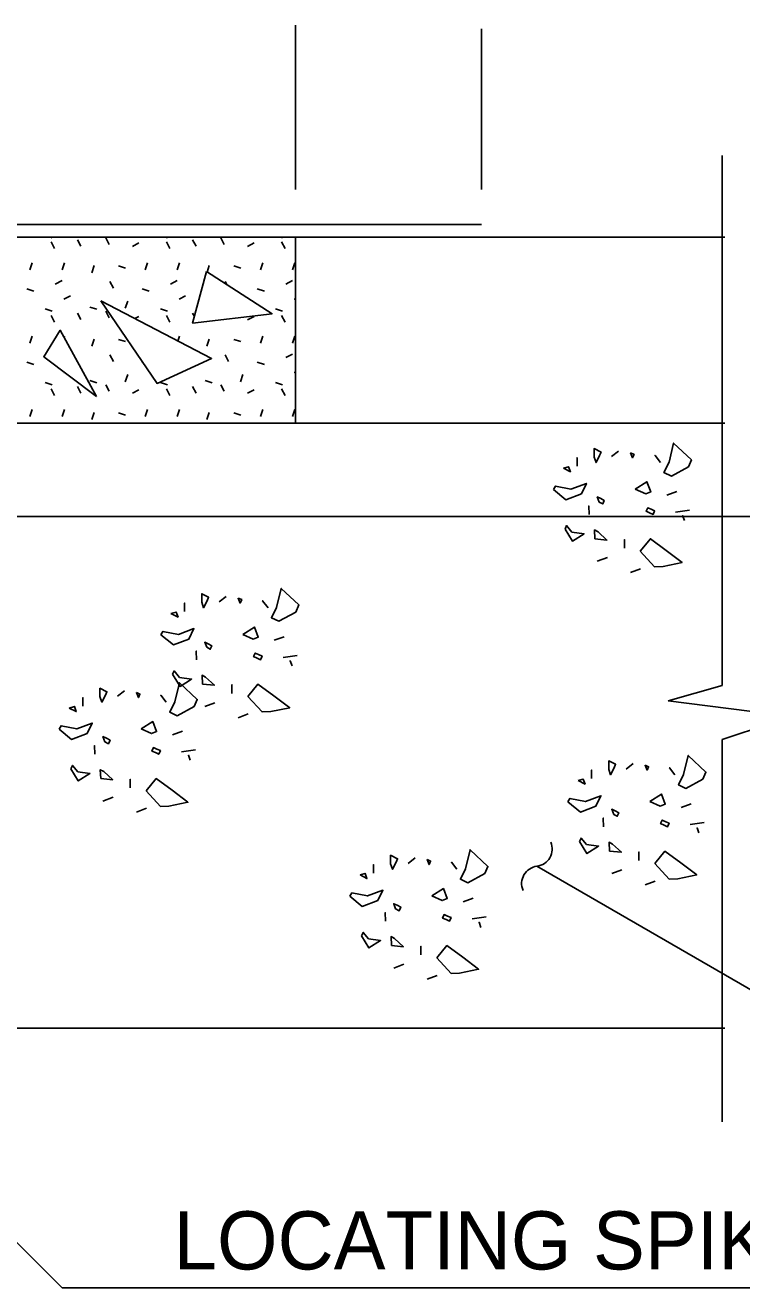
# Model space of a CAD drawing. Extents: x 0 to 11.3, y 0 to 7.8.
# Drawn here: x 3.931 to 4.573, y 1.625 to 2.755 of the extents above; entities that cross this region are included whole.
import ezdxf

# ---------------------------------------------------------------- set-up
doc = ezdxf.new("R2010")
doc.units = 0
for name, color, linetype in [('BRDG_ANNO_General-Notes', 7, 'Continuous'), ('BRDG_BASE_Obj-Line', 7, 'Continuous'), ('BRDG_BASE_Pattern', 7, 'Continuous')]:
    doc.layers.add(name, color=color, linetype=linetype)

msp = doc.modelspace()

# ---------------------------------------------------------------- linework, layer by layer
at = {"layer": 'BRDG_ANNO_General-Notes'}
for p, q in [((4.1734, 2.6081), (4.1734, 2.7552)), ((4.3401, 2.6081), (4.3401, 2.7519)), ((3.4093, 2.3154), (4.8358, 2.3154)), ((3.3467, 2.2423), (3.9645, 1.6245)), ((4.7803, 1.7765), (4.3897, 2.002)), ((4.6945, 1.6245), (3.9645, 1.6245))]:
    msp.add_line(p, q, dxfattribs=at)
for centre, start, end in [((4.3878, 2.0175), 276.8706, 23.1308), ((4.3916, 1.9865), 96.8706, 203.1308)]:
    msp.add_arc(centre, 0.0156, start, end, dxfattribs=at)
at = {"layer": 'BRDG_BASE_Obj-Line'}
for p, q in [((4.5557, 2.6385), (4.5557, 2.164)), ((4.3401, 2.5769), (2.3401, 2.5769)), ((2.5067, 2.5654), (4.1734, 2.5654)), ((3.954, 2.5654), (3.9557, 2.5648)), ((3.9547, 2.5611), (3.9578, 2.5552)), ((3.9782, 2.5631), (3.9812, 2.5573)), ((4.0065, 2.5589), (4.0035, 2.5648)), ((4.0332, 2.5602), (4.0274, 2.5572)), ((4.0571, 2.5654), (4.0589, 2.5648)), ((4.0579, 2.5611), (4.0609, 2.5552)), ((4.0814, 2.5631), (4.0844, 2.5573)), ((4.1097, 2.5589), (4.1067, 2.5648)), ((4.1364, 2.5602), (4.1306, 2.5572)), ((4.1603, 2.5654), (4.162, 2.5648)), ((4.1611, 2.5611), (4.1641, 2.5552)), ((4.5581, 2.5654), (4.1734, 2.5654)), ((4.1734, 2.3987), (4.1734, 2.5654)), ((3.9377, 2.5425), (3.9357, 2.5362)), ((3.9665, 2.5424), (3.9644, 2.5361)), ((3.991, 2.5336), (3.9931, 2.5399)), ((4.0214, 2.5376), (4.0151, 2.5396)), ((4.0409, 2.5425), (4.0389, 2.5362)), ((4.0696, 2.5424), (4.0676, 2.5361)), ((4.0944, 2.5342), (4.0963, 2.5399)), ((4.1245, 2.5376), (4.1183, 2.5396)), ((4.1441, 2.5425), (4.1421, 2.5362)), ((4.1728, 2.5424), (4.1707, 2.5361)), ((3.9644, 2.5265), (3.9584, 2.5234)), ((4.0104, 2.5198), (4.0073, 2.5257)), ((4.0676, 2.5265), (4.0616, 2.5234)), ((4.1119, 2.523), (4.1105, 2.5257)), ((4.1707, 2.5265), (4.1648, 2.5234)), ((3.9329, 2.5191), (3.9392, 2.5171)), ((3.966, 2.5098), (3.9719, 2.5129)), ((4.0361, 2.5191), (4.0424, 2.5171)), ((4.0692, 2.5098), (4.0751, 2.5129)), ((4.1393, 2.5191), (4.1456, 2.5171)), ((4.1724, 2.5098), (4.1734, 2.5103)), ((3.9494, 2.5011), (3.9557, 2.4991)), ((3.9957, 2.5008), (3.9894, 2.5028)), ((4.0065, 2.4931), (4.0035, 2.4991)), ((4.0211, 2.5018), (4.0232, 2.5081)), ((4.0526, 2.5011), (4.0589, 2.4991)), ((4.1557, 2.5011), (4.162, 2.4991)), ((3.9547, 2.4954), (3.9578, 2.4894)), ((3.9782, 2.4974), (3.9812, 2.4916)), ((4.0332, 2.4945), (4.0296, 2.4926)), ((4.0579, 2.4954), (4.0609, 2.4894)), ((4.0814, 2.4974), (4.083, 2.4943)), ((4.1364, 2.4945), (4.1306, 2.4915)), ((4.1611, 2.4954), (4.1641, 2.4894)), ((3.9377, 2.4768), (3.9357, 2.4705)), ((3.9665, 2.4767), (3.9662, 2.4759)), ((4.0696, 2.4767), (4.0682, 2.4724)), ((4.1441, 2.4768), (4.1421, 2.4705)), ((4.1728, 2.4767), (4.1707, 2.4704)), ((3.991, 2.4679), (3.9931, 2.4742)), ((4.0214, 2.4719), (4.0151, 2.4739)), ((4.0942, 2.4679), (4.0963, 2.4742)), ((4.1245, 2.4719), (4.1183, 2.4739)), ((4.0104, 2.4541), (4.0073, 2.4599)), ((4.1135, 2.4541), (4.1105, 2.4599)), ((4.1707, 2.4607), (4.1648, 2.4577)), ((3.9329, 2.4534), (3.9392, 2.4514)), ((3.966, 2.4441), (3.9666, 2.4443)), ((4.0211, 2.436), (4.0232, 2.4423)), ((4.0361, 2.4534), (4.0368, 2.4532)), ((4.1243, 2.436), (4.1264, 2.4423)), ((4.1393, 2.4534), (4.1456, 2.4514)), ((4.1724, 2.4441), (4.1734, 2.4446)), ((3.9494, 2.4354), (3.9557, 2.4333)), ((3.9782, 2.4317), (3.9812, 2.4258)), ((3.9957, 2.4351), (3.9894, 2.4371)), ((4.0065, 2.4274), (4.0035, 2.4333)), ((4.0526, 2.4354), (4.0589, 2.4333)), ((4.0814, 2.4317), (4.0844, 2.4258)), ((4.0989, 2.4351), (4.0926, 2.4371)), ((4.1097, 2.4274), (4.1067, 2.4333)), ((4.1557, 2.4354), (4.162, 2.4333)), ((3.9547, 2.4296), (3.9578, 2.4237)), ((4.0332, 2.4287), (4.0274, 2.4257)), ((4.0579, 2.4296), (4.0609, 2.4237)), ((4.1364, 2.4287), (4.1306, 2.4257)), ((4.1611, 2.4296), (4.1641, 2.4237)), ((3.9377, 2.411), (3.9357, 2.4048)), ((3.9665, 2.411), (3.9644, 2.4047)), ((3.991, 2.4021), (3.9931, 2.4084)), ((4.0409, 2.411), (4.0389, 2.4048)), ((4.0696, 2.411), (4.0676, 2.4047)), ((4.0942, 2.4021), (4.0963, 2.4084)), ((4.1441, 2.411), (4.1421, 2.4048)), ((4.1728, 2.411), (4.1707, 2.4047)), ((4.5581, 2.3987), (3.4234, 2.3987)), ((4.0214, 2.4061), (4.0151, 2.4081)), ((4.1245, 2.4061), (4.1183, 2.4081)), ((4.5071, 2.1501), (4.5557, 2.164)), ((4.6182, 2.1362), (4.5071, 2.1501)), ((4.5557, 2.1154), (4.6182, 2.1362)), ((4.5557, 2.1154), (4.5557, 1.773)), ((4.5581, 1.857), (3.4234, 1.857))]:
    msp.add_line(p, q, dxfattribs=at)
for points in [[(2.5067, 2.5654), (4.1734, 2.5654), (4.1734, 2.3987), (2.5067, 2.3987)], [(4.0939, 2.5346), (4.1526, 2.4968), (4.0814, 2.4884)], [(3.9991, 2.5085), (4.0984, 2.4567), (4.0495, 2.4344)], [(3.9954, 2.4228), (3.9628, 2.482), (3.948, 2.4583)]]:
    msp.add_lwpolyline(points, close=True, dxfattribs=at)
at = {"layer": 'BRDG_BASE_Pattern'}
for p, q in [((4.4566, 2.3689), (4.4628, 2.3737)), ((4.5059, 2.3345), (4.5149, 2.3376)), ((4.5139, 2.3192), (4.5264, 2.3209)), ((4.4437, 2.2751), (4.4528, 2.2786)), ((4.4736, 2.2651), (4.4826, 2.2685)), ((4.1051, 2.2388), (4.1114, 2.2436)), ((4.1544, 2.2044), (4.1634, 2.2075)), ((4.1624, 2.1891), (4.1749, 2.1908)), ((4.014, 2.1542), (4.0203, 2.1591)), ((4.0922, 2.145), (4.1013, 2.1485)), ((4.1221, 2.1349), (4.1311, 2.1384)), ((4.0633, 2.1198), (4.0723, 2.1229)), ((4.0713, 2.1045), (4.0838, 2.1062)), ((4.4696, 2.0891), (4.4758, 2.094)), ((4.0011, 2.0604), (4.0102, 2.0639)), ((4.5189, 2.0547), (4.5279, 2.0579)), ((4.031, 2.0504), (4.0401, 2.0539)), ((4.5269, 2.0395), (4.5394, 2.0412)), ((4.2743, 2.0046), (4.2806, 2.0095)), ((4.4567, 1.9954), (4.4658, 1.9989)), ((4.4866, 1.9853), (4.4956, 1.9888)), ((4.3236, 1.9702), (4.3327, 1.9733)), ((4.3316, 1.9549), (4.3441, 1.9567)), ((4.2615, 1.9108), (4.2705, 1.9143)), ((4.2914, 1.9008), (4.3004, 1.9043))]:
    msp.add_line(p, q, dxfattribs=at)
for points in [[(4.4409, 2.3685), (4.4427, 2.3636), (4.4458, 2.3699), (4.4472, 2.373), (4.4409, 2.3761)], [(4.508, 2.364), (4.5034, 2.3546), (4.5101, 2.3515), (4.5253, 2.3598), (4.5281, 2.3661), (4.5121, 2.381)], [(4.4257, 2.3602), (4.4257, 2.3678)], [(4.4736, 2.3723), (4.4753, 2.3678), (4.4767, 2.3709), (4.4767, 2.3709), (4.4767, 2.3709), (4.4767, 2.3709), (4.4736, 2.3723), (4.4736, 2.3723)], [(4.5003, 2.3636), (4.4955, 2.3699)], [(4.4135, 2.3584), (4.4197, 2.3553), (4.418, 2.3598)], [(4.4045, 2.3394), (4.4156, 2.3303), (4.4295, 2.3355), (4.434, 2.3449), (4.4201, 2.3397), (4.4062, 2.3425)], [(4.4778, 2.3397), (4.4871, 2.3355), (4.4916, 2.3373), (4.4882, 2.3463)], [(4.4455, 2.3282), (4.4486, 2.3265), (4.4486, 2.3265), (4.4499, 2.3296), (4.4499, 2.3296), (4.4468, 2.3314), (4.4468, 2.3314), (4.4437, 2.3328), (4.4437, 2.3328), (4.4455, 2.3282)], [(4.4364, 2.3171), (4.4361, 2.3248)], [(4.4906, 2.3185), (4.4937, 2.3171), (4.4951, 2.3203), (4.4951, 2.3203), (4.492, 2.3217), (4.492, 2.3217), (4.4889, 2.323), (4.4889, 2.323), (4.4889, 2.323), (4.4874, 2.3199)], [(4.4149, 2.304), (4.4215, 2.2932), (4.4319, 2.2998), (4.4211, 2.3011), (4.4163, 2.3071)], [(4.5218, 2.3116), (4.5201, 2.3161)], [(4.4416, 2.2953), (4.4524, 2.2942), (4.4524, 2.2942), (4.4444, 2.3015), (4.4413, 2.3032)], [(4.468, 2.2869), (4.468, 2.2946)], [(4.4822, 2.2842), (4.4951, 2.2703), (4.5028, 2.2706), (4.5197, 2.2741), (4.5055, 2.2848), (4.4913, 2.2953)], [(4.1565, 2.2339), (4.152, 2.2245), (4.1586, 2.2214), (4.1739, 2.2297), (4.1766, 2.236), (4.1607, 2.2509)], [(4.0895, 2.2384), (4.0912, 2.2335), (4.0943, 2.2398), (4.0957, 2.2429), (4.0895, 2.246)], [(4.1221, 2.2422), (4.1239, 2.2377), (4.1253, 2.2408), (4.1253, 2.2408), (4.1253, 2.2408), (4.1253, 2.2408), (4.1221, 2.2422), (4.1221, 2.2422)], [(4.1489, 2.2335), (4.144, 2.2398)], [(4.062, 2.2283), (4.0683, 2.2252), (4.0666, 2.2297)], [(4.0742, 2.2301), (4.0742, 2.2377)], [(4.1263, 2.2096), (4.1357, 2.2054), (4.1402, 2.2072), (4.1367, 2.2162)], [(4.053, 2.2093), (4.0641, 2.2002), (4.078, 2.2054), (4.0826, 2.2148), (4.0686, 2.2096), (4.0547, 2.2124)], [(4.0849, 2.187), (4.0846, 2.1947)], [(4.094, 2.1981), (4.0971, 2.1964), (4.0971, 2.1964), (4.0985, 2.1995), (4.0985, 2.1995), (4.0954, 2.2012), (4.0954, 2.2012), (4.0922, 2.2027), (4.0922, 2.2027), (4.094, 2.1981)], [(4.1391, 2.1884), (4.1422, 2.187), (4.1436, 2.1902), (4.1436, 2.1902), (4.1405, 2.1916), (4.1405, 2.1916), (4.1374, 2.1929), (4.1374, 2.1929), (4.1374, 2.1929), (4.136, 2.1898)], [(4.1704, 2.1815), (4.1686, 2.186)], [(4.0634, 2.1739), (4.0701, 2.1631), (4.0805, 2.1697), (4.0697, 2.171), (4.0648, 2.177)], [(4.0902, 2.1652), (4.1009, 2.1641), (4.1009, 2.1641), (4.093, 2.1714), (4.0898, 2.1731)], [(3.9984, 2.1539), (4.0001, 2.149), (4.0032, 2.1552), (4.0046, 2.1583), (3.9984, 2.1615)], [(4.0654, 2.1493), (4.0609, 2.1399), (4.0675, 2.1368), (4.0828, 2.1452), (4.0855, 2.1514), (4.0696, 2.1664)], [(4.1166, 2.1568), (4.1166, 2.1645)], [(4.1308, 2.1541), (4.1436, 2.1402), (4.1513, 2.1405), (4.1683, 2.144), (4.1541, 2.1547), (4.1398, 2.1652)], [(3.9831, 2.1455), (3.9831, 2.1531)], [(4.031, 2.1577), (4.0328, 2.1531), (4.0342, 2.1562), (4.0342, 2.1562), (4.0342, 2.1562), (4.0342, 2.1562), (4.031, 2.1577), (4.031, 2.1577)], [(4.0578, 2.149), (4.0529, 2.1552)], [(3.9709, 2.1437), (3.9772, 2.1406), (3.9755, 2.1452)], [(3.9619, 2.1247), (3.973, 2.1156), (3.9869, 2.1208), (3.9915, 2.1302), (3.9776, 2.125), (3.9636, 2.1278)], [(4.0352, 2.125), (4.0446, 2.1208), (4.0491, 2.1226), (4.0456, 2.1316)], [(4.0029, 2.1135), (4.006, 2.1118), (4.006, 2.1118), (4.0074, 2.1149), (4.0074, 2.1149), (4.0043, 2.1167), (4.0043, 2.1167), (4.0011, 2.1181), (4.0011, 2.1181), (4.0029, 2.1135)], [(3.9939, 2.1024), (3.9935, 2.1101)], [(4.048, 2.1039), (4.0511, 2.1024), (4.0526, 2.1056), (4.0526, 2.1056), (4.0494, 2.107), (4.0494, 2.107), (4.0463, 2.1083), (4.0463, 2.1083), (4.0463, 2.1083), (4.0449, 2.1052)], [(3.9723, 2.0893), (3.979, 2.0785), (3.9894, 2.0851), (3.9786, 2.0865), (3.9737, 2.0924)], [(4.0793, 2.0969), (4.0776, 2.1014)], [(4.454, 2.0888), (4.4557, 2.0839), (4.4588, 2.0902), (4.4602, 2.0933), (4.454, 2.0964)], [(4.4866, 2.0926), (4.4883, 2.0881), (4.4897, 2.0912), (4.4897, 2.0912), (4.4897, 2.0912), (4.4897, 2.0912), (4.4866, 2.0926), (4.4866, 2.0926)], [(4.521, 2.0843), (4.5165, 2.0749), (4.5231, 2.0718), (4.5383, 2.0801), (4.5411, 2.0864), (4.5252, 2.1013)], [(3.9991, 2.0806), (4.0098, 2.0795), (4.0098, 2.0795), (4.0019, 2.0868), (3.9987, 2.0885)], [(4.0397, 2.0695), (4.0526, 2.0556), (4.0602, 2.0559), (4.0772, 2.0594), (4.063, 2.0702), (4.0488, 2.0806)], [(4.4387, 2.0805), (4.4387, 2.0881)], [(4.5133, 2.0839), (4.5085, 2.0902)], [(4.0255, 2.0722), (4.0255, 2.0799)], [(4.4265, 2.0787), (4.4328, 2.0756), (4.431, 2.0801)], [(4.4175, 2.0596), (4.4286, 2.0506), (4.4425, 2.0558), (4.447, 2.0652), (4.4331, 2.0599), (4.4192, 2.0628)], [(4.4908, 2.0599), (4.5002, 2.0558), (4.5046, 2.0576), (4.5012, 2.0666)], [(4.4585, 2.0485), (4.4616, 2.0468), (4.4616, 2.0468), (4.463, 2.0499), (4.463, 2.0499), (4.4598, 2.0516), (4.4598, 2.0516), (4.4567, 2.053), (4.4567, 2.053), (4.4585, 2.0485)], [(4.4494, 2.0374), (4.4491, 2.0451)], [(4.5036, 2.0388), (4.5067, 2.0374), (4.5081, 2.0405), (4.5081, 2.0405), (4.505, 2.0419), (4.505, 2.0419), (4.5019, 2.0433), (4.5019, 2.0433), (4.5019, 2.0433), (4.5005, 2.0402)], [(4.5348, 2.0318), (4.5331, 2.0364)], [(4.4279, 2.0242), (4.4345, 2.0134), (4.4449, 2.0201), (4.4342, 2.0214), (4.4293, 2.0273)], [(4.3257, 1.9997), (4.3212, 1.9904), (4.3278, 1.9872), (4.3431, 1.9956), (4.3458, 2.0018), (4.3299, 2.0168)], [(4.4546, 2.0155), (4.4654, 2.0145), (4.4654, 2.0145), (4.4574, 2.0218), (4.4543, 2.0235)], [(4.481, 2.0072), (4.481, 2.0148)], [(4.4953, 2.0044), (4.5081, 1.9905), (4.5158, 1.9909), (4.5328, 1.9943), (4.5185, 2.0051), (4.5043, 2.0155)], [(4.2434, 1.9959), (4.2434, 2.0035)], [(4.2587, 2.0043), (4.2604, 1.9994), (4.2635, 2.0056), (4.2649, 2.0088), (4.2587, 2.0119)], [(4.2914, 2.0081), (4.2931, 2.0035), (4.2945, 2.0067), (4.2945, 2.0067), (4.2945, 2.0067), (4.2945, 2.0067), (4.2914, 2.0081), (4.2914, 2.0081)], [(4.3181, 1.9994), (4.3132, 2.0056)], [(4.2313, 1.9942), (4.2375, 1.991), (4.2358, 1.9956)], [(4.2222, 1.9751), (4.2333, 1.966), (4.2472, 1.9712), (4.2518, 1.9806), (4.2379, 1.9754), (4.224, 1.9782)], [(4.2955, 1.9754), (4.3049, 1.9712), (4.3094, 1.973), (4.3059, 1.982)], [(4.2632, 1.964), (4.2664, 1.9622), (4.2664, 1.9622), (4.2677, 1.9654), (4.2677, 1.9654), (4.2646, 1.9671), (4.2646, 1.9671), (4.2615, 1.9685), (4.2615, 1.9685), (4.2632, 1.964)], [(4.2542, 1.9529), (4.2539, 1.9605)], [(4.3083, 1.9543), (4.3115, 1.9529), (4.3129, 1.956), (4.3129, 1.956), (4.3097, 1.9574), (4.3097, 1.9574), (4.3066, 1.9587), (4.3066, 1.9587), (4.3066, 1.9587), (4.3052, 1.9556)], [(4.3396, 1.9473), (4.3379, 1.9518)], [(4.2327, 1.9397), (4.2393, 1.9289), (4.2497, 1.9355), (4.2389, 1.9369), (4.2341, 1.9428)], [(4.2594, 1.931), (4.2702, 1.9299), (4.2702, 1.9299), (4.2622, 1.9372), (4.2591, 1.939)], [(4.2858, 1.9227), (4.2858, 1.9303)], [(4.3, 1.9199), (4.3129, 1.906), (4.3205, 1.9064), (4.3375, 1.9098), (4.3233, 1.9206), (4.3091, 1.931)]]:
    msp.add_lwpolyline(points, close=True, dxfattribs=at)

# ---------------------------------------------------------------- texts
at = {"layer": 'BRDG_ANNO_General-Notes'}
msp.add_text('LOCATING SPIKE', height=0.052083, dxfattribs=at).set_placement((4.0645, 1.6409))

doc.saveas('drawing.dxf')
